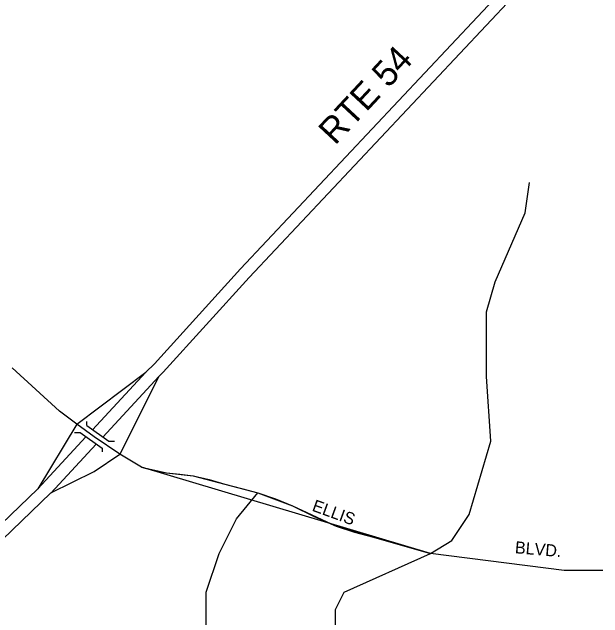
# Model space of a CAD drawing. Extents: x 5.01 to 9.58, y 0.27 to 3.39.
# Drawn here: x 8.037 to 8.571, y 1.311 to 1.858 of the extents above; entities that cross this region are included whole.
import ezdxf

# ---------------------------------------------------------------- set-up
doc = ezdxf.new("R2010")
doc.units = 0
doc.layers.add('MO_001_NOSHOW', color=7, linetype='Continuous')
doc.layers.add('MO_001_VIEW_PV', color=7, linetype='Continuous')

msp = doc.modelspace()

# ---------------------------------------------------------------- linework, layer by layer
at = {"layer": 'MO_001_NOSHOW'}
msp.add_lwpolyline([(8.15355, 1.44686), (8.17629, 1.44167), (8.20032, 1.43906), (8.22895, 1.43148), (8.25879, 1.42348), (8.28998, 1.41178), (8.32953, 1.39343), (8.36317, 1.38358), (8.41472, 1.3689)], close=True, dxfattribs=at)
at = {"layer": 'MO_001_VIEW_PV'}
for p, q in [((8.07951, 1.49752), (8.03662, 1.5365)), ((8.09502, 1.48578), (8.15749, 1.53259)), ((8.10922, 1.48056), (8.15749, 1.53259)), ((8.1185, 1.47404), (8.16908, 1.52867)), ((8.16908, 1.52867), (8.13401, 1.45853)), ((8.09502, 1.48578), (8.05995, 1.42737)), ((8.10401, 1.48461), (8.10401, 1.48824)), ((8.10401, 1.48461), (8.12416, 1.47041)), ((8.05995, 1.42737), (8.10328, 1.47419)), ((8.09314, 1.4781), (8.09806, 1.4781)), ((8.09806, 1.4781), (8.11807, 1.46403)), ((8.12416, 1.47041), (8.12923, 1.47041)), ((8.07168, 1.42346), (8.11256, 1.46766)), ((8.11807, 1.46403), (8.11807, 1.46056))]:
    msp.add_line(p, q, dxfattribs=at)
for points in [[(8.15744, 1.53262), (8.16524, 1.54041), (8.2432, 1.62617), (8.48098, 1.87955), (8.53945, 1.9497), (8.54894, 1.95919)], [(8.16913, 1.52872), (8.17303, 1.53262), (8.251, 1.61838), (8.48878, 1.87176), (8.55114, 1.94191), (8.55872, 1.95137)], [(8.47318, 1.61448), (8.50047, 1.67684), (8.50438, 1.70414)], [(8.44979, 1.40397), (8.46929, 1.47025), (8.46539, 1.52872), (8.46539, 1.58718), (8.47318, 1.61448)], [(8.15355, 1.44686), (8.13406, 1.45856), (8.11066, 1.47414), (8.09508, 1.48583), (8.07948, 1.49753)], [(8.07168, 1.42348), (8.11066, 1.44296), (8.13406, 1.45856)], [(8.15355, 1.44686), (8.16483, 1.44386), (8.17629, 1.44167), (8.18832, 1.44044), (8.20032, 1.43906), (8.21471, 1.4357), (8.22895, 1.43148), (8.24389, 1.4275), (8.25879, 1.42348), (8.27458, 1.41818), (8.28998, 1.41178), (8.30964, 1.40225), (8.32953, 1.39343), (8.34618, 1.38809), (8.36317, 1.38358), (8.38898, 1.37631), (8.41472, 1.3689)], [(7.72882, 0.918), (7.74814, 1.06875), (7.77153, 1.13112), (7.79492, 1.1662), (7.85338, 1.22857), (8.05999, 1.42737)], [(7.73995, 0.9151), (7.74035, 0.91672), (7.75983, 1.06484), (7.78323, 1.12331), (7.80272, 1.1584), (7.86119, 1.22076), (8.07168, 1.42348)], [(8.2432, 1.10773), (8.23151, 1.135), (8.21591, 1.17399), (8.21201, 1.21297), (8.21201, 1.33382), (8.22372, 1.3689), (8.23931, 1.40008), (8.25879, 1.42348)], [(8.41472, 1.3689), (8.43421, 1.38059), (8.44979, 1.40397)], [(8.32896, 1.29465), (8.32896, 1.31821), (8.33676, 1.33382), (8.41472, 1.3689)], [(8.57063, 1.3533), (8.53555, 1.3533), (8.41472, 1.3689)]]:
    msp.add_lwpolyline(points, dxfattribs=at)

# ---------------------------------------------------------------- texts
for s, height, rotation, p in [('RTE 54', 0.023189, 47, (8.32854, 1.73724)), ('ELLIS', 0.01087, 340, (8.307, 1.40762)), ('BLVD.', 0.01087, 355, (8.49081, 1.36908))]:
    msp.add_text(s, height=height, rotation=rotation, dxfattribs=at).set_placement(p)

doc.saveas('drawing.dxf')
